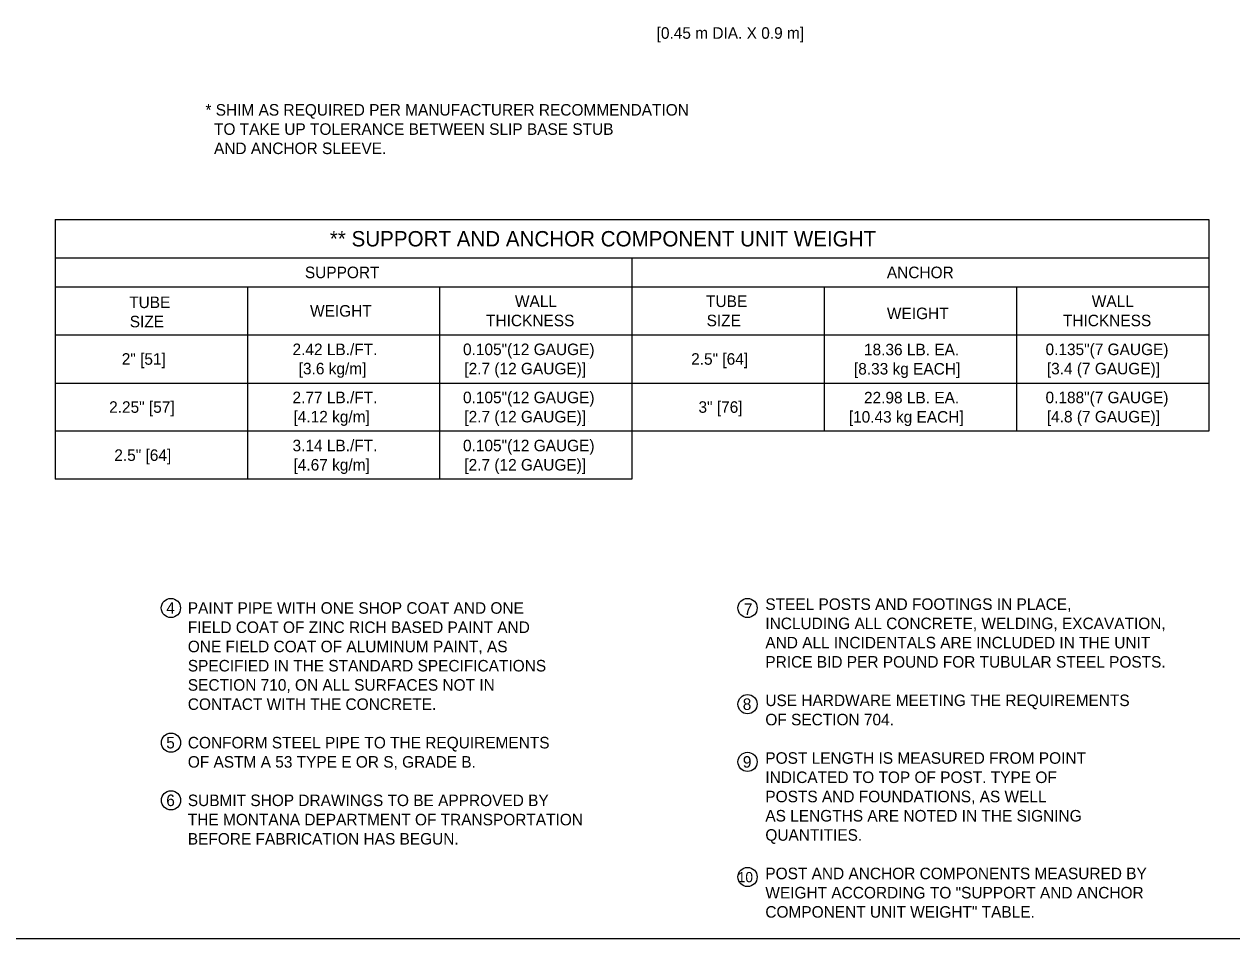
# Model space of a CAD drawing. Extents: x 49940 to 50043, y 49986 to 50011.
# Drawn here: x 50004.91 to 50011.19, y 49987.8 to 49992.55 of the extents above; entities that cross this region are included whole.
import ezdxf

# ---------------------------------------------------------------- set-up
doc = ezdxf.new("R2010")
doc.units = 0
doc.layers.add('Level 1', color=7, linetype='Continuous')
doc.layers.add('Level 2', color=7, linetype='Continuous')

msp = doc.modelspace()

# ---------------------------------------------------------------- linework, layer by layer
at = {"layer": 'Level 1'}
msp.add_lwpolyline([(49999.3835, 49998.9992), (50016.7501, 49998.9992), (50016.7501, 49987.7988), (49999.3835, 49987.7988)], close=True, dxfattribs=at)
at = {"layer": 'Level 2'}
for p, q in [((50005.0668, 49991.5385), (50011.0668, 49991.5385)), ((50005.0668, 49991.5385), (50005.0668, 49990.1885)), ((50011.0668, 49991.5385), (50011.0668, 49990.4385)), ((50005.0668, 49991.3385), (50011.0668, 49991.3385)), ((50008.0668, 49991.3385), (50008.0668, 49990.1885)), ((50005.0668, 49991.1885), (50011.0668, 49991.1885)), ((50006.0668, 49991.1885), (50006.0668, 49990.1885)), ((50006.4699, 49991.1885), (50006.4699, 49991.1885)), ((50007.0668, 49991.1885), (50007.0668, 49990.1885)), ((50008.0668, 49991.1885), (50008.0668, 49991.1885)), ((50009.0668, 49991.1885), (50009.0668, 49990.4364)), ((50010.0668, 49991.1885), (50010.0668, 49990.4364)), ((50005.0668, 49990.9385), (50011.0668, 49990.9385)), ((50006.4699, 49990.9385), (50006.4699, 49990.9385)), ((50007.2699, 49990.9385), (50007.2699, 49990.9385)), ((50008.0668, 49990.9385), (50008.0668, 49990.9385)), ((50008.8668, 49990.9385), (50008.8668, 49990.9385)), ((50009.6668, 49990.9385), (50009.6668, 49990.9385)), ((50007.8388, 49990.7883), (50007.8388, 49990.7883)), ((50005.0668, 49990.6885), (50011.0668, 49990.6885)), ((50006.4699, 49990.6885), (50006.4699, 49990.6885)), ((50007.2699, 49990.6885), (50007.2699, 49990.6885)), ((50008.0668, 49990.6885), (50008.0668, 49990.6885)), ((50008.8668, 49990.6885), (50008.8668, 49990.6885)), ((50009.6668, 49990.6885), (50009.6668, 49990.6885)), ((50007.8388, 49990.4888), (50007.8388, 49990.4888)), ((50011.0668, 49990.4385), (50005.0668, 49990.4385)), ((50008.0668, 49990.1885), (50005.0668, 49990.1885))]:
    msp.add_line(p, q, dxfattribs=at)
for centre in [(50005.6691, 49989.5188), (50008.6681, 49989.5188), (50008.6681, 49989.0188), (50005.6698, 49988.8188), (50008.6681, 49988.7188), (50005.6698, 49988.5188), (50008.6681, 49988.1203)]:
    msp.add_circle(centre, 0.05, dxfattribs=at)

# ---------------------------------------------------------------- texts
for s, height, p in [('[0.45 m DIA. X 0.9 m]', 0.06, (50008.1953, 49992.4781)), ('* SHIM AS REQUIRED PER MANUFACTURER RECOMMENDATION ', 0.06, (50005.8488, 49992.0786)), ('  TO TAKE UP TOLERANCE BETWEEN SLIP BASE STUB ', 0.06, (50005.8488, 49991.9786)), ('  AND ANCHOR SLEEVE.', 0.06, (50005.8488, 49991.8786)), ('** SUPPORT AND ANCHOR COMPONENT UNIT WEIGHT', 0.08, (50006.4957, 49991.3985)), ('SUPPORT', 0.06, (50006.3661, 49991.2335)), ('ANCHOR', 0.06, (50009.3927, 49991.2335)), ('TUBE', 0.06, (50005.4524, 49991.078)), ('WEIGHT', 0.06, (50006.3929, 49991.0335)), ('WALL', 0.06, (50007.4585, 49991.0835)), ('TUBE', 0.06, (50008.4524, 49991.0835)), ('WALL', 0.06, (50010.4585, 49991.0835)), ('SIZE', 0.06, (50005.4553, 49990.978)), ('THICKNESS', 0.06, (50007.3083, 49990.9835)), ('SIZE', 0.06, (50008.4553, 49990.9835)), ('WEIGHT', 0.06, (50009.3929, 49991.0205)), ('THICKNESS', 0.06, (50010.3083, 49990.9835)), ('2" [51]', 0.06, (50005.4136, 49990.7835)), ('2.42 LB./FT.', 0.06, (50006.3018, 49990.8335)), ('0.105"(12 GAUGE)', 0.06, (50007.1884, 49990.8335)), ('2.5" [64]', 0.06, (50008.3749, 49990.7835)), ('18.36 LB. EA.', 0.06, (50009.2736, 49990.8325)), ('0.135"(7 GAUGE)', 0.06, (50010.2178, 49990.8335)), ('[3.6 kg/m]', 0.06, (50006.3338, 49990.7335)), ('[2.7 (12 GAUGE)]', 0.06, (50007.1953, 49990.7335)), ('[8.33 kg EACH]', 0.06, (50009.2214, 49990.7325)), ('[3.4 (7 GAUGE)]', 0.06, (50010.2246, 49990.7335)), ('2.25" [57]', 0.06, (50005.3479, 49990.5335)), ('2.77 LB./FT.', 0.06, (50006.3018, 49990.5835)), ('0.105"(12 GAUGE)', 0.06, (50007.1884, 49990.5835)), ('3" [76]', 0.06, (50008.4129, 49990.5335)), ('22.98 LB. EA.', 0.06, (50009.2736, 49990.5825)), ('0.188"(7 GAUGE)', 0.06, (50010.2178, 49990.5835)), ('[4.12 kg/m]', 0.06, (50006.3069, 49990.4835)), ('[2.7 (12 GAUGE)]', 0.06, (50007.1953, 49990.4835)), ('[10.43 kg EACH]', 0.06, (50009.1945, 49990.4825)), ('[4.8 (7 GAUGE)]', 0.06, (50010.2246, 49990.4835)), ('2.5" [64]', 0.06, (50005.3749, 49990.2835)), ('3.14 LB./FT.', 0.06, (50006.3018, 49990.3335)), ('0.105"(12 GAUGE)', 0.06, (50007.1884, 49990.3335)), ('[4.67 kg/m]', 0.06, (50006.3069, 49990.2335)), ('[2.7 (12 GAUGE)]', 0.06, (50007.1953, 49990.2335)), ('4', 0.06, (50005.6451, 49989.4888)), ('PAINT PIPE WITH ONE SHOP COAT AND ONE', 0.06, (50005.7572, 49989.4888)), ('7', 0.06, (50008.6492, 49989.4831)), ('STEEL POSTS AND FOOTINGS IN PLACE,', 0.06, (50008.7607, 49989.5088)), ('INCLUDING ALL CONCRETE, WELDING, EXCAVATION,', 0.06, (50008.7607, 49989.4088)), ('FIELD COAT OF ZINC RICH BASED PAINT AND', 0.06, (50005.7572, 49989.3888)), ('ONE FIELD COAT OF ALUMINUM PAINT, AS', 0.06, (50005.7572, 49989.2888)), ('AND ALL INCIDENTALS ARE INCLUDED IN THE UNIT ', 0.06, (50008.7607, 49989.3088)), ('PRICE BID PER POUND FOR TUBULAR STEEL POSTS.', 0.06, (50008.7607, 49989.2088)), ('SPECIFIED IN THE STANDARD SPECIFICATIONS', 0.06, (50005.7572, 49989.1888)), ('SECTION 710, ON ALL SURFACES NOT IN', 0.06, (50005.7572, 49989.0888)), ('CONTACT WITH THE CONCRETE.', 0.06, (50005.7572, 49988.9888)), ('8', 0.06, (50008.6431, 49988.9888)), ('USE HARDWARE MEETING THE REQUIREMENTS ', 0.06, (50008.7607, 49989.0088)), ('OF SECTION 704. ', 0.06, (50008.7607, 49988.9088)), ('5', 0.06, (50005.6449, 49988.7888)), ('CONFORM STEEL PIPE TO THE REQUIREMENTS', 0.06, (50005.7572, 49988.7888)), ('POST LENGTH IS MEASURED FROM POINT', 0.06, (50008.7607, 49988.7088)), ('OF ASTM A 53 TYPE E OR S, GRADE B.', 0.06, (50005.7572, 49988.6888)), ('9', 0.06, (50008.6436, 49988.6888)), ('INDICATED TO TOP OF POST. TYPE OF ', 0.06, (50008.7607, 49988.6088)), ('6', 0.06, (50005.6452, 49988.4888)), ('SUBMIT SHOP DRAWINGS TO BE APPROVED BY', 0.06, (50005.7572, 49988.4888)), ('POSTS AND FOUNDATIONS, AS WELL', 0.06, (50008.7607, 49988.5088)), ('AS LENGTHS ARE NOTED IN THE SIGNING', 0.06, (50008.7607, 49988.4088)), ('THE MONTANA DEPARTMENT OF TRANSPORTATION', 0.06, (50005.7572, 49988.3888)), ('BEFORE FABRICATION HAS BEGUN.', 0.06, (50005.7572, 49988.2888)), ('QUANTITIES.', 0.06, (50008.7607, 49988.3088)), ('10', 0.05338, (50008.6171, 49988.0929)), ('POST AND ANCHOR COMPONENTS MEASURED BY ', 0.06, (50008.7607, 49988.1088)), ('WEIGHT ACCORDING TO "SUPPORT AND ANCHOR', 0.06, (50008.7607, 49988.0088)), ('COMPONENT UNIT WEIGHT" TABLE.', 0.06, (50008.7607, 49987.9088))]:
    msp.add_text(s, height=height, dxfattribs=at).set_placement(p)

doc.saveas('drawing.dxf')
